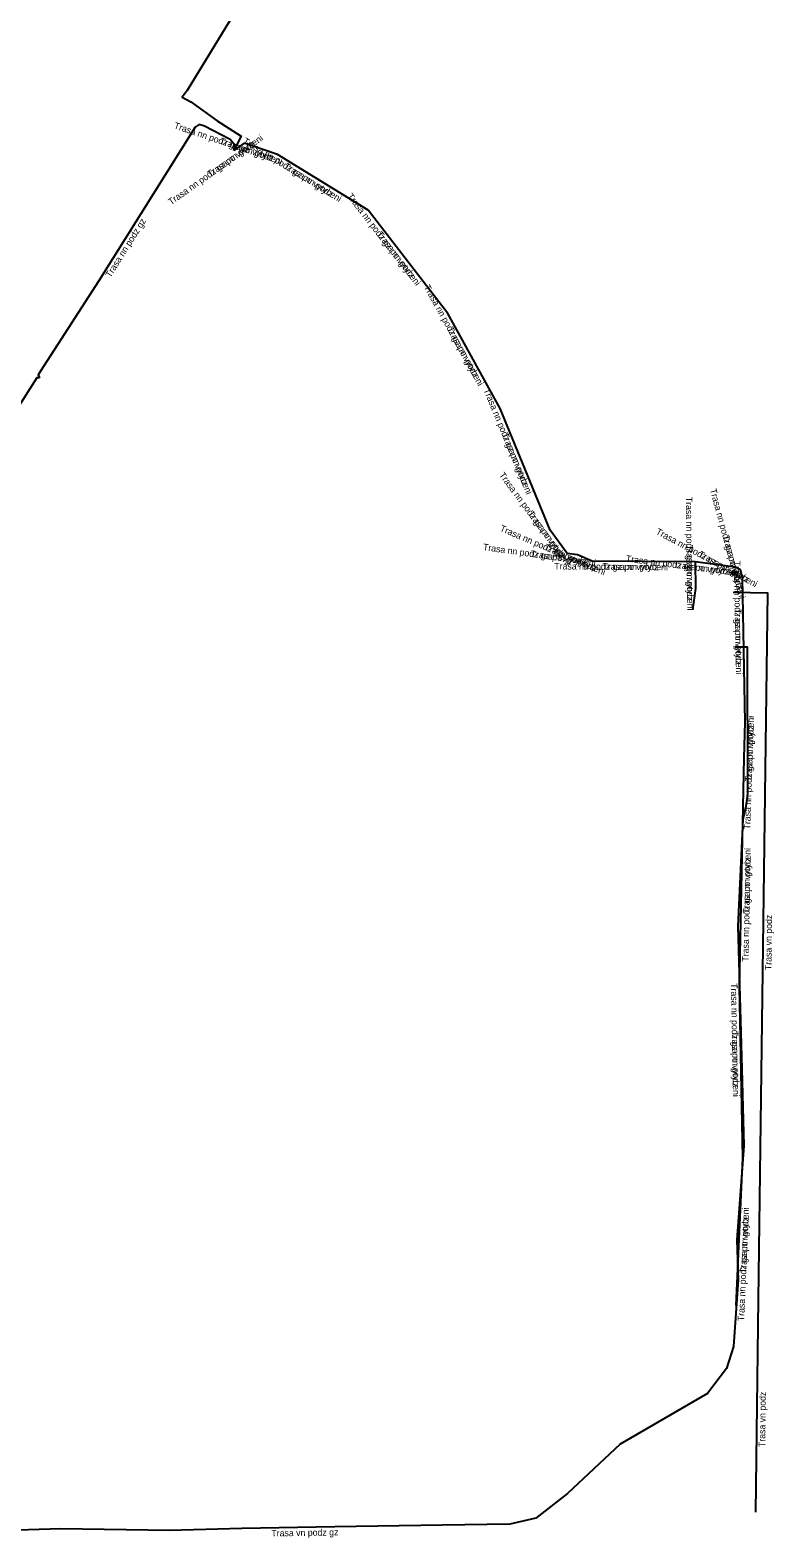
# Model space of a CAD drawing. Extents: x -672293 to -672171, y -1013397 to -1013222.
# Drawn here: x -672228 to -672171.1, y -1013397.1 to -1013281.7 of the extents above; entities that cross this region are included whole.
import ezdxf

# ---------------------------------------------------------------- set-up
doc = ezdxf.new("R2010")
doc.units = 0
for name, color, linetype in [('Popiskový text - Ostatní atributy Trasy', 7, 'Continuous'), ('Spojnice NN', 7, 'Continuous'), ('Spojnice VN', 7, 'Continuous')]:
    doc.layers.add(name, color=color, linetype=linetype)

msp = doc.modelspace()

# ---------------------------------------------------------------- linework, layer by layer
at = {"layer": 'Spojnice NN'}
for points in [[(-672211.42, -1013243.28), (-672210.46, -1013247.66), (-672209.07, -1013253.47), (-672214.26, -1013261.49), (-672220.27, -1013270.05), (-672221.87, -1013272.45), (-672221.65, -1013272.98), (-672220.88, -1013273.48), (-672212.57, -1013278.32), (-672212.07, -1013278.85), (-672211.77, -1013279.37), (-672212.45, -1013280.52), (-672215.95, -1013286.28), (-672216.33, -1013286.81), (-672215.69, -1013287.16), (-672213.67, -1013288.62), (-672211.83, -1013289.8), (-672212.39, -1013290.88)], [(-672212.39, -1013290.88), (-672212.3, -1013290.47), (-672212.67, -1013290.05), (-672214.63, -1013289.01), (-672215.04, -1013288.9), (-672215.36, -1013289.1), (-672222.72, -1013300.85), (-672227.19, -1013307.78), (-672227.35, -1013308.06), (-672227.26, -1013308.27)], [(-672211.6, -1013290.32), (-672212.39, -1013290.88)], [(-672211.6, -1013290.32), (-672212.39, -1013290.88)], [(-672209.05, -1013291.18), (-672211.6, -1013290.32)], [(-672209.05, -1013291.18), (-672211.6, -1013290.32)], [(-672202.11, -1013295.45), (-672209.05, -1013291.18)], [(-672202.11, -1013295.45), (-672209.05, -1013291.18)], [(-672196, -1013303.36), (-672202.11, -1013295.45)], [(-672196, -1013303.36), (-672202.11, -1013295.45)], [(-672192, -1013310.64), (-672196, -1013303.36)], [(-672192, -1013310.64), (-672196, -1013303.36)], [(-672227.26, -1013308.27), (-672227.46, -1013308.28), (-672227.64, -1013308.56), (-672232.4, -1013316.03), (-672232.48, -1013316.38), (-672232.3, -1013316.49)], [(-672188.19, -1013319.94), (-672192, -1013310.64)], [(-672188.19, -1013319.94), (-672192, -1013310.64)], [(-672186.87, -1013321.72), (-672188.19, -1013319.94)], [(-672186.87, -1013321.72), (-672188.19, -1013319.94)], [(-672186.09, -1013321.83), (-672186.87, -1013321.72)], [(-672186.09, -1013321.83), (-672186.87, -1013321.72)], [(-672184.97, -1013322.31), (-672186.09, -1013321.83)], [(-672184.97, -1013322.31), (-672186.09, -1013321.83)], [(-672177.09, -1013322.37), (-672184.97, -1013322.31)], [(-672177.09, -1013322.37), (-672184.97, -1013322.31)], [(-672177.09, -1013322.37), (-672177.06, -1013324.41), (-672177.29, -1013326.04)], [(-672177.09, -1013322.37), (-672177.06, -1013324.41), (-672177.29, -1013326.04)], [(-672174.01, -1013322.76), (-672177.09, -1013322.37)], [(-672174.01, -1013322.76), (-672177.09, -1013322.37)], [(-672173.62, -1013322.97), (-672174.01, -1013322.76)], [(-672173.62, -1013322.97), (-672174.01, -1013322.76)], [(-672173.46, -1013323.56), (-672173.62, -1013322.97)], [(-672173.46, -1013323.56), (-672173.62, -1013322.97)], [(-672173.25, -1013334.64), (-672173.46, -1013323.56)], [(-672173.25, -1013334.64), (-672173.46, -1013323.56)], [(-672173.34, -1013337.35), (-672173.25, -1013334.64)], [(-672173.34, -1013337.35), (-672173.25, -1013334.64)], [(-672173.69, -1013354.88), (-672173.34, -1013337.35)], [(-672173.69, -1013354.88), (-672173.34, -1013337.35)], [(-672173.45, -1013367.98), (-672173.69, -1013354.88)], [(-672173.45, -1013367.98), (-672173.69, -1013354.88)], [(-672173.94, -1013379.27), (-672173.45, -1013367.98)], [(-672173.94, -1013379.27), (-672173.45, -1013367.98)]]:
    msp.add_lwpolyline(points, dxfattribs=at)
at = {"layer": 'Spojnice VN'}
for points in [[(-672172.24, -1013378.82), (-672171.52, -1013324.75), (-672174.18, -1013324.72)], [(-672174.03, -1013328.88), (-672173.11, -1013328.88), (-672173.07, -1013340.12), (-672173.22, -1013341.09), (-672173.45, -1013342.08), (-672173.82, -1013350.24), (-672173.59, -1013358.35), (-672173.52, -1013361.17), (-672173.35, -1013367.06), (-672173.9, -1013374.26), (-672173.79, -1013377.31), (-672174.16, -1013382.41), (-672174.7, -1013384.1), (-672176.13, -1013386), (-672182.82, -1013389.89), (-672186.86, -1013393.66), (-672189.27, -1013395.55), (-672191.27, -1013396.01), (-672196.45, -1013396.08), (-672204.67, -1013396.22), (-672211.78, -1013396.34), (-672217.3, -1013396.48), (-672225.64, -1013396.36), (-672231.43, -1013396.54)], [(-672172.45, -1013395.09), (-672172.24, -1013378.82)]]:
    msp.add_lwpolyline(points, dxfattribs=at)

# ---------------------------------------------------------------- texts
at = {"layer": 'Popiskový text - Ostatní atributy Trasy'}
for s, rotation, p in [('Trasa nn podz gz po vytyceni', 341.3631, (-672217.01, -1013289.18)), ('Trasa nn podz gz po vytyceni', 35.3313, (-672217.19, -1013295.08)), ('Trasa nn podz', 35.3313, (-672214.19, -1013292.95)), ('Trasa nn podz', 341.3631, (-672213.52, -1013290.36)), ('Trasa nn podz gz po vytyceni', 328.3971, (-672211.74, -1013290.29)), ('Trasa nn podz', 328.3971, (-672208.6, -1013292.22)), ('Trasa nn podz gz po vytyceni', 307.6839, (-672203.75, -1013294.4)), ('Trasa nn podz gz', 57.9377, (-672221.83, -1013300.65)), ('Trasa nn podz', 307.6839, (-672201.49, -1013297.31)), ('Trasa nn podz gz po vytyceni', 298.7866, (-672197.86, -1013301.33)), ('Trasa nn podz', 298.7866, (-672196.09, -1013304.55)), ('Trasa nn podz gz po vytyceni', 292.2778, (-672193.29, -1013309.21)), ('Trasa nn podz', 292.2778, (-672191.89, -1013312.62)), ('Trasa nn podz gz po vytyceni', 306.5596, (-672192.12, -1013315.73)), ('Trasa nn podz gz po vytyceni', 285.1729, (-672175.96, -1013316.84)), ('Trasa nn podz gz po vytyceni', 270.725, (-672177.8, -1013317.39)), ('Trasa nn podz', 306.5596, (-672189.93, -1013318.69)), ('Trasa nn podz gz po vytyceni', 336.8014, (-672192.07, -1013319.98)), ('Trasa nn podz gz po vytyceni', 331.6992, (-672180.14, -1013320.2)), ('Trasa nn podz', 285.1729, (-672174.99, -1013320.4)), ('Trasa nn podz gz po vytyceni', 351.9728, (-672193.34, -1013321.46)), ('Trasa nn podz', 351.9728, (-672189.69, -1013321.98)), ('Trasa nn podz', 336.8014, (-672188.68, -1013321.43)), ('Trasa nn podz', 270.725, (-672177.76, -1013321.07)), ('Trasa nn podz', 331.6992, (-672176.89, -1013321.94)), ('Trasa nn podz gz po vytyceni', 359.5637, (-672187.87, -1013322.94)), ('Trasa nn podz', 359.5637, (-672184.18, -1013322.97)), ('Trasa nn podz gz po vytyceni', 352.7834, (-672182.41, -1013322.35)), ('Trasa nn podz', 352.7834, (-672178.75, -1013322.81)), ('Trasa nn podz gz po vytyceni', 271.0858, (-672174.13, -1013322.28)), ('Trasa nn podz', 271.0858, (-672174.06, -1013325.97)), ('Trasa nn podz gz po vytyceni', 88.0979, (-672172.87, -1013342.85)), ('Trasa nn podz', 88.0979, (-672172.75, -1013339.16)), ('Trasa nn podz gz po vytyceni', 88.8562, (-672173, -1013352.96)), ('Trasa nn podz', 88.8562, (-672172.93, -1013349.28)), ('Trasa vn podz', 89.2447, (-672171.25, -1013353.61)), ('Trasa nn podz gz po vytyceni', 271.0496, (-672174.35, -1013354.61)), ('Trasa nn podz', 271.0496, (-672174.28, -1013358.29)), ('Trasa nn podz gz po vytyceni', 87.5149, (-672173.34, -1013380.48)), ('Trasa nn podz', 87.5149, (-672173.18, -1013376.8)), ('Trasa vn podz', 89.2448, (-672171.73, -1013390.11)), ('Trasa vn podz gz', 0.9669, (-672209.51, -1013396.95))]:
    msp.add_text(s, height=0.5, rotation=rotation, dxfattribs=at).set_placement(p)

doc.saveas('drawing.dxf')
